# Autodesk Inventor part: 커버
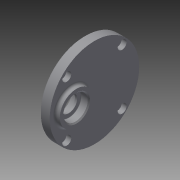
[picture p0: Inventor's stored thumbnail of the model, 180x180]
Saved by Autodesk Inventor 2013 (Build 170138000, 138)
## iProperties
Created: 2015-07
Part Number: 커버
Material: 일반
Document SubType Name: Modeling
Designer: user
Density: 1 g/cm^3
Author: user
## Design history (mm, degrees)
sketch "스케치1"
  geometry: C1 r 40 at (0, 0); 1 further point
  constraints: 1 centre point, 1 coincident
  dimensions: "d0" = 80 diameter of C1
extrude "돌출1" new body sketch "스케치1" distance "d1" = 9; taper "d2" = 0 deg
sketch "스케치2"
  geometry: L1 (0, 0)-(0, 11); L2 (0, 0)-(0, -20); C1 r 40 at (0, 0) reference; C2 r 14 at (0, 11); C3 r 14 at (0, -20)
  constraints: 4 end point, 2 centre point, 2 coincident, 1 collinear, 1 vertical
  dimensions: "d3" = 11 distance of L1.start L1.end; "d4" = 20 distance of L1.start L2.end; "d5" = 28 diameter of C2; "d6" = 28 diameter of C3
extrude "돌출2" join sketch "스케치2" distance "d7" = 3; taper "d8" = 0 deg
sketch "스케치3"
  geometry: L1 (0, 0)-(0, -20); C1 r 40 at (0, 0) reference; C2 r 15 at (0, -20)
  constraints: 2 end point, 1 centre point, 1 coincident, 1 vertical
  dimensions: "d9" = 20 distance of L1.start L1.end; "d10" = 30 diameter of C2
extrude "돌출3" join sketch "스케치3" distance "d11" = 4; taper "d12" = 0 deg
sketch "스케치4"
  geometry: C1 r 15 at (0, 0) reference; C2 r 11 at (0, 0); 1 further point
  constraints: 1 centre point, 1 coincident
  dimensions: "d13" = 22 diameter of C2
extrude "돌출4" cut sketch "스케치4" distance "d14" = 7; taper "d15" = 0 deg
sketch "스케치5"
  geometry: C1 r 14 at (0, 0) reference; C2 r 11 at (0, 0); 1 further point
  constraints: 1 centre point, 1 coincident
  dimensions: "d16" = 22 diameter of C2
extrude "돌출5" cut sketch "스케치5" distance "d17" = 7; taper "d18" = 0 deg
sketch "스케치6"
  geometry: C1 r 11 at (0, 0) reference; C2 r 7.5 at (0, 0); 1 further point
  constraints: 1 centre point, 1 coincident
  dimensions: "d19" = 15 diameter of C2
extrude "돌출6" cut sketch "스케치6" distance "d20" = 2; taper "d21" = 0 deg
sketch "스케치7"
  geometry: C1 r 14 at (0, 0) reference; C2 r 11 at (0, 0); 1 further point
  constraints: 1 centre point, 1 coincident
  dimensions: "d22" = 22 diameter of C2
extrude "돌출7" cut sketch "스케치7" distance "d23" = 7; taper "d24" = 0 deg
sketch "스케치8"
  geometry: C1 r 9 at (0, 0); 2 further points
  constraints: 1 centre point, 1 coincident, 1 vertical alignment
  dimensions: "d25" = 18 diameter of C1
extrude "돌출8" cut sketch "스케치8" distance "d26" = 1; taper "d27" = 0 deg
fillet "모깎기1" dims "d28" = 2
fillet "모깎기2" dims "d29" = 0.3
chamfer "모따기1" distance "d30" = 1; stored, may be unused: second distance "d31" = 2, angle "d32" = 45 deg
chamfer "모따기2" distance "d33" = 1; stored, may be unused: second distance "d34" = 2, angle "d35" = 45 deg
fillet "모깎기3" dims "d36" = 2
chamfer "모따기3" distance "d37" = 1; stored, may be unused: second distance "d38" = 2, angle "d39" = 45 deg
sketch "스케치9" dims "d40" = 70
  geometry: L1 (0, 0)-(24.749, 24.749); L2 (0, 0)-(35, 0); C1 r 40 at (0, 0) reference; C2 r 4 at (24.749, 24.749)
  constraints: 4 end point, 2 coincident, 1 centre point, 1 equal length, 1 horizontal, 3 other
  dimensions: "d41" = 45 deg angle of L2 L1; "d42" = 8 diameter of C2
extrude "돌출9" cut sketch "스케치9" distance "d43" = 4.4; taper "d44" = 0 deg
sketch "스케치10"
  geometry: C1 r 4 at (0, 0) reference; C2 r 2.25 at (0, 0); 1 further point
  constraints: 1 centre point, 1 coincident
  dimensions: "d45" = 4.5 diameter of C2
extrude "돌출10" cut sketch "스케치10" stored distance "d46" = 4.4; taper "d47" = 0 deg
node "솔리드1"
pattern_circular "원형 패턴1" dims angle "d49" = 360 deg
